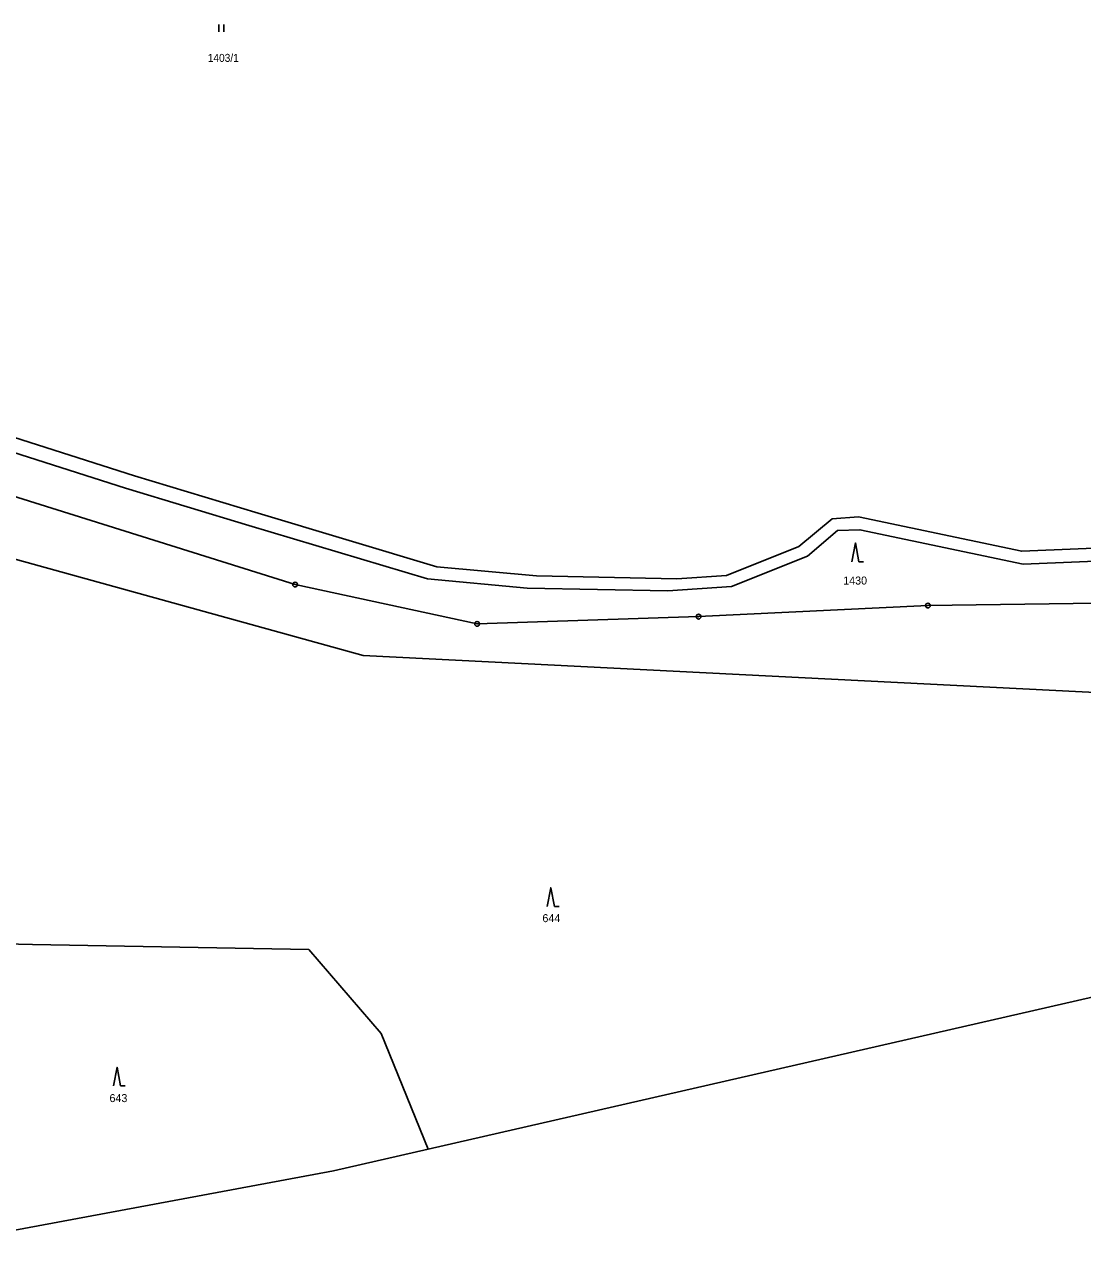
# Model space of a CAD drawing. Extents: x -872229 to -869198, y -1075981 to -1074329.
# Drawn here: x -870264.8 to -870040, y -1075773.8 to -1075512.3 of the extents above; entities that cross this region are included whole.
import ezdxf

# ---------------------------------------------------------------- set-up
doc = ezdxf.new("R2010")
doc.units = 0
doc.header["$LTSCALE"] = 0.68
for name, color, linetype, lineweight in [('1', 7, 'Continuous', 25), ('3', 7, 'Continuous', 25), ('8', 7, 'Continuous', 25)]:
    doc.layers.add(name, color=color, linetype=linetype, lineweight=lineweight)
doc.layers.add('2', color=7, linetype='Continuous')

msp = doc.modelspace()

# ---------------------------------------------------------------- linework, layer by layer
at = {"layer": '1'}
for points in [[(-870360.91, -1075564.7), (-870334.21, -1075571.6), (-870312.37, -1075586.81), (-870293.77, -1075595.76), (-870270.86, -1075602.02), (-870243.34, -1075610.77), (-870217.09, -1075618.71), (-870179.15, -1075630.08), (-870157.97, -1075632.03), (-870128.13, -1075632.63), (-870114.57, -1075631.72), (-870098.39, -1075625.25), (-870092.04, -1075619.77), (-870087.29, -1075619.63), (-870052.6, -1075626.97), (-870018.4, -1075625.53), (-869988.87, -1075627.77), (-869967.84, -1075631.16), (-869962.49, -1075632.97), (-869956.97, -1075636.94), (-869956.21, -1075634.42)], [(-869956.21, -1075634.42), (-869961.39, -1075630.69), (-869968.14, -1075628.41), (-869989.17, -1075625.02), (-870018.7, -1075622.78), (-870052.9, -1075624.22), (-870087.59, -1075616.88), (-870093.16, -1075617.33), (-870100.3, -1075623.21), (-870115.61, -1075629.33), (-870126.17, -1075630.04), (-870156.01, -1075629.44), (-870177.19, -1075627.49), (-870215.13, -1075616.12), (-870241.38, -1075608.18), (-870268.9, -1075599.43), (-870291.81, -1075593.17), (-870310.41, -1075584.22), (-870332.25, -1075569.01)], [(-870319.49, -1075589.3), (-870295.19, -1075603.73), (-870207.28, -1075631.27), (-870168.61, -1075639.64), (-870121.56, -1075638.1), (-870072.83, -1075635.74), (-870016.23, -1075634.96), (-869958.54, -1075642.14), (-869957.53, -1075638.79), (-869956.97, -1075636.94)], [(-869946.97, -1075719.04), (-869951.52, -1075667.78), (-870006.44, -1075655.77), (-870192.84, -1075646.38), (-870362.26, -1075599.45), (-870356.17, -1075620.52)], [(-870179.01, -1075751.24), (-870188.98, -1075726.65), (-870204.4, -1075708.79), (-870263.11, -1075707.73), (-870292.9, -1075707.03), (-870321.66, -1075708.31)], [(-870179.01, -1075751.24), (-870035.17, -1075718.28), (-870015.01, -1075718.11)], [(-870295.8, -1075773.81), (-870199.13, -1075755.85), (-870179.01, -1075751.24)]]:
    msp.add_lwpolyline(points, dxfattribs=at)
at = {"layer": '3'}
for p, q in [((-870223.461, -1075513.81), (-870223.461, -1075512.31)), ((-870222.46, -1075513.81), (-870222.46, -1075512.31)), ((-870087.51, -1075626.42), (-870086.514, -1075626.42)), ((-870152.21, -1075699.71), (-870151.214, -1075699.71)), ((-870244.36, -1075737.82), (-870243.364, -1075737.82))]:
    msp.add_line(p, q, dxfattribs=at)
for points in [[(-870087.51, -1075626.42), (-870088.26, -1075622.42), (-870089.01, -1075626.42)], [(-870152.21, -1075699.71), (-870152.96, -1075695.71), (-870153.71, -1075699.71)], [(-870244.36, -1075737.82), (-870245.11, -1075733.82), (-870245.86, -1075737.82)]]:
    msp.add_lwpolyline(points, dxfattribs=at)
at = {"layer": '8'}
for centre, radius in [((-870207.28, -1075631.2699), 0.5), ((-870207.28, -1075631.2699), 0.0303), ((-870072.83, -1075635.7399), 0.5), ((-870072.83, -1075635.7399), 0.0303), ((-870121.56, -1075638.0999), 0.5), ((-870121.56, -1075638.0999), 0.0303), ((-870168.61, -1075639.6399), 0.5), ((-870168.61, -1075639.6399), 0.0303)]:
    msp.add_circle(centre, radius, dxfattribs=at)

# ---------------------------------------------------------------- texts
at = {"layer": '2', "width": 0.95}
msp.add_text('1403/1', height=1.7, dxfattribs=at).set_placement((-870225.85, -1075520.23))
at = {"layer": '2'}
for s, p in [('1430', (-870090.83, -1075631.28)), ('644', (-870154.74, -1075703.01)), ('643', (-870246.72, -1075741.24))]:
    msp.add_text(s, height=1.7, dxfattribs=at).set_placement(p)

doc.saveas('drawing.dxf')
